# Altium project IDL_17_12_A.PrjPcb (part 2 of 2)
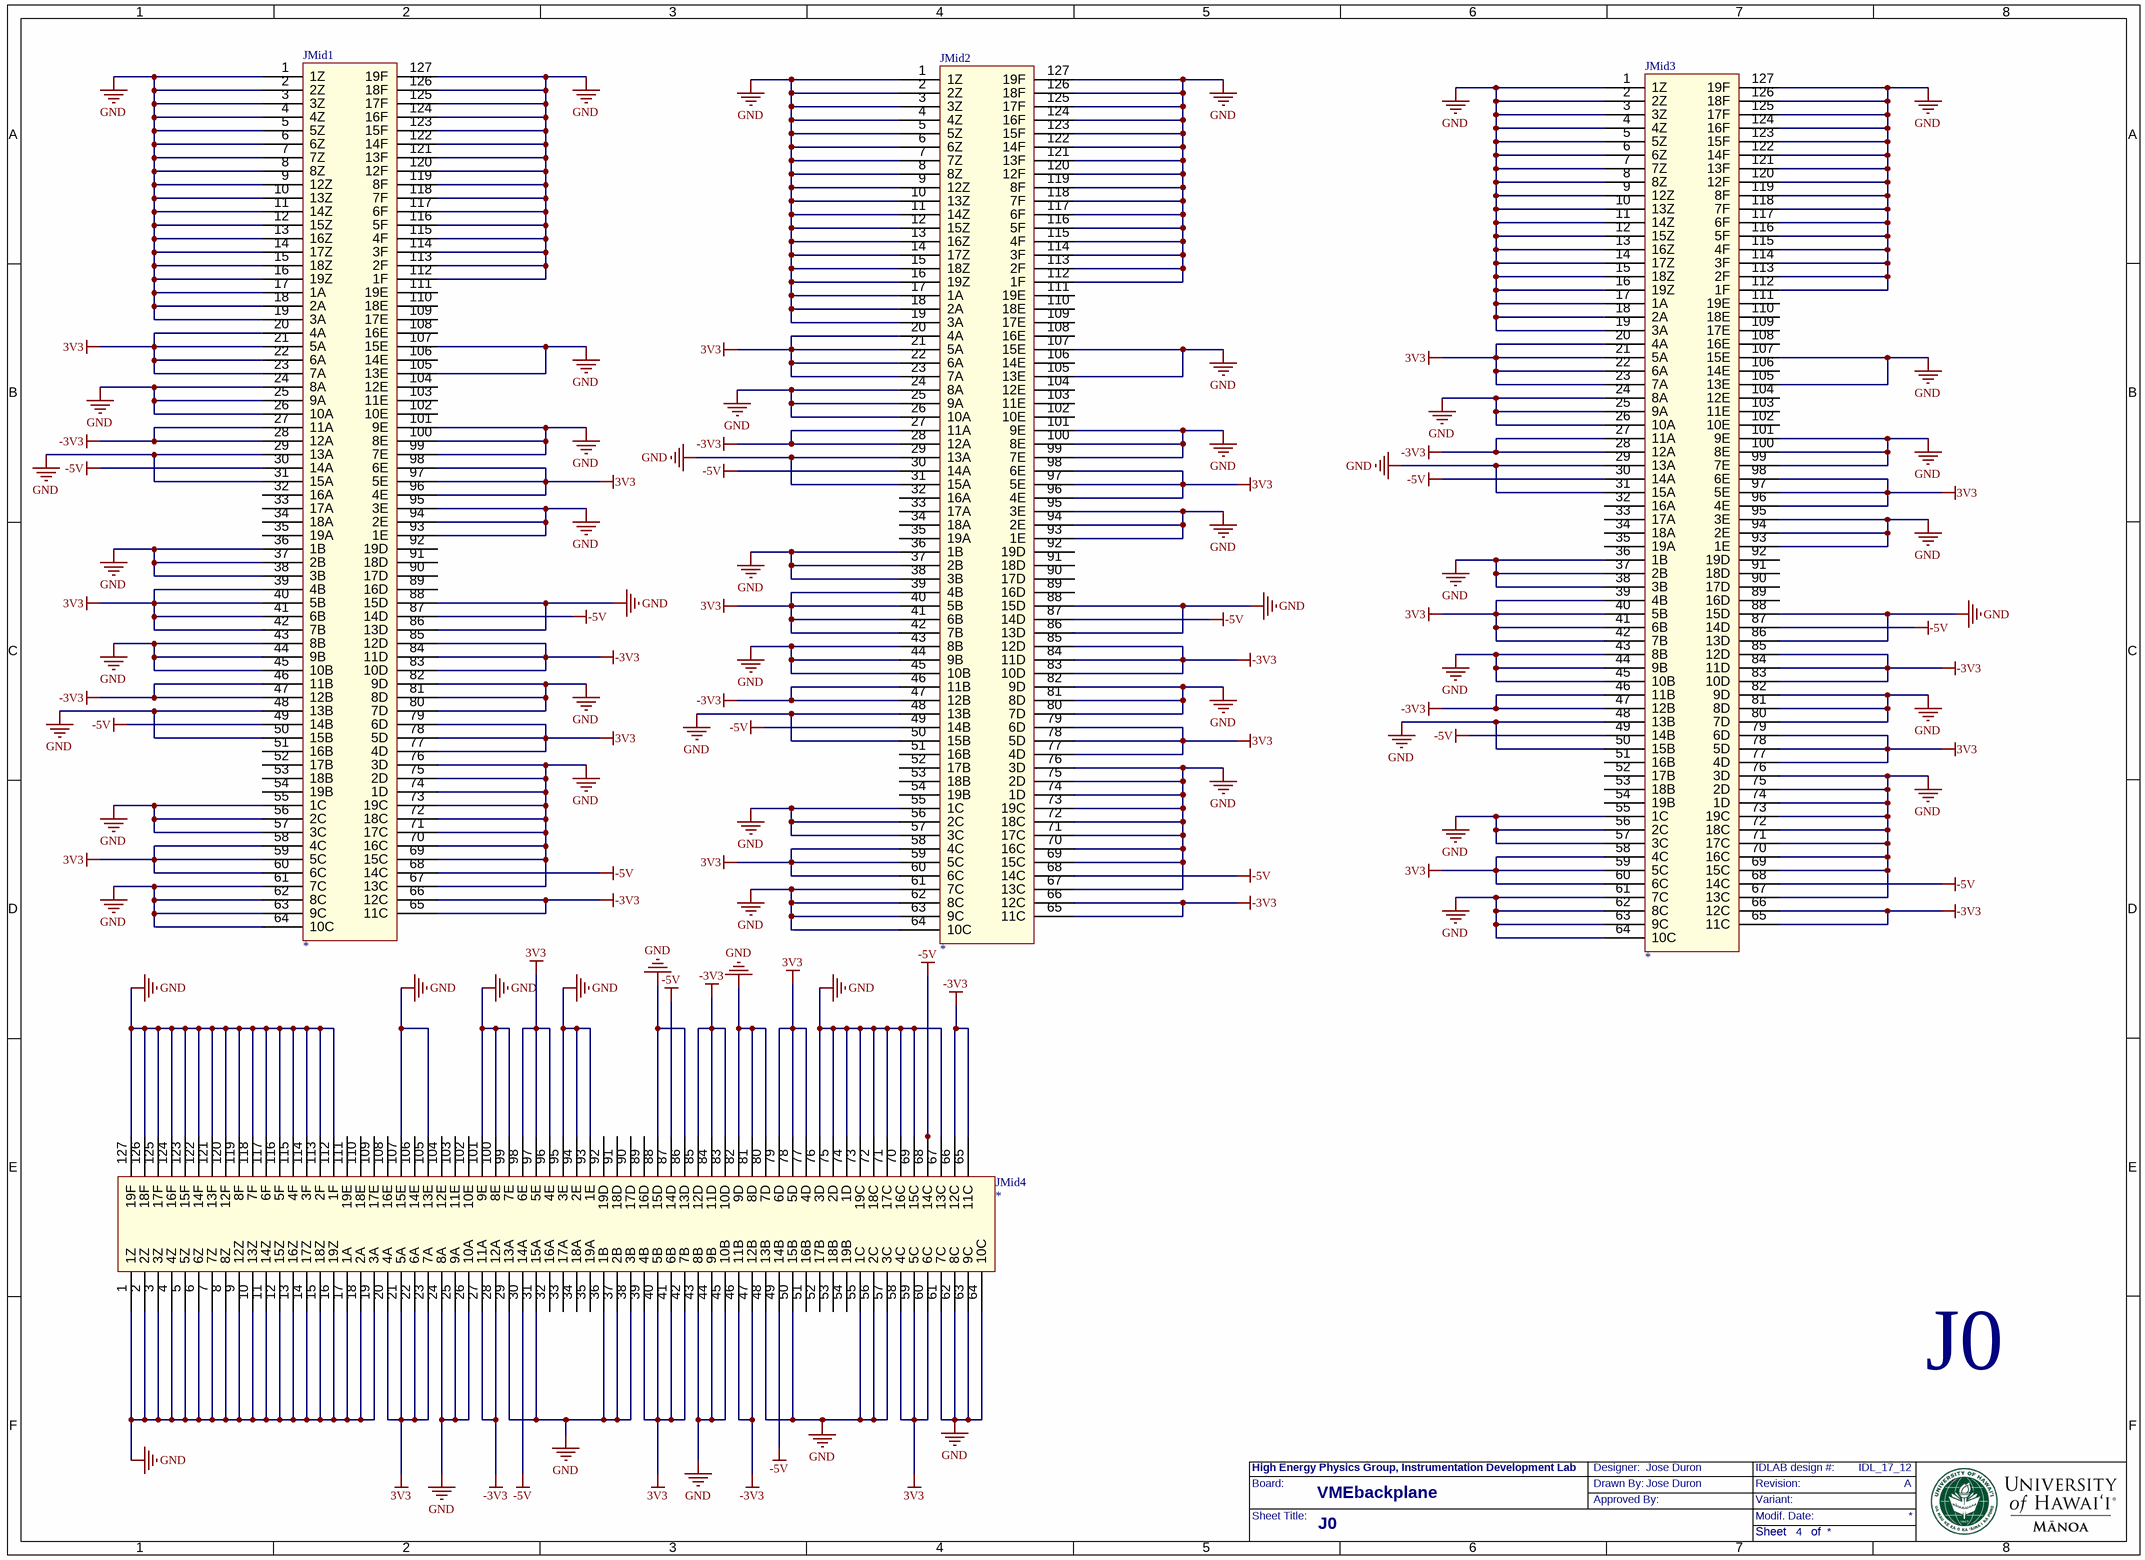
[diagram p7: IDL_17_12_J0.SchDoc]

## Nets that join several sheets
3V3: IDL_17_12_Top (5 pins), IDL_17_12_J0 (68 pins)
5V: IDL_17_12_Top (5 pins), IDL_17_12_J1 (16 pins), IDL_17_12_J2 (12 pins), IDL_IDL_17_12_VME/IDL_17_12_TerA1 (CR_IDL_17_12_TerA1.2 R1R_IDL_17_12_TerA1.2), IDL_IDL_17_12_VME/IDL_17_12_TerA2 (CR_IDL_17_12_TerA2.2 R1R_IDL_17_12_TerA2.2), IDL_IDL_17_12_VME/IDL_17_12_TerA3 (CR_IDL_17_12_TerA3.2 R1R_IDL_17_12_TerA3.2), IDL_IDL_17_12_VME/IDL_17_12_TerA4 (CR_IDL_17_12_TerA4.2 R1R_IDL_17_12_TerA4.2), IDL_IDL_17_12_VME/IDL_17_12_TerA5 (CR_IDL_17_12_TerA5.2 R1R_IDL_17_12_TerA5.2), IDL_IDL_17_12_VME/IDL_17_12_TerA6 (CR_IDL_17_12_TerA6.2 R1R_IDL_17_12_TerA6.2), IDL_IDL_17_12_VME/IDL_17_12_TerA7 (CR_IDL_17_12_TerA7.2 R1R_IDL_17_12_TerA7.2), IDL_IDL_17_12_VME/IDL_17_12_TerA8 (CR_IDL_17_12_TerA8.2 R1R_IDL_17_12_TerA8.2), IDL_IDL_17_12_VME/IDL_17_12_TerA9 (CR_IDL_17_12_TerA9.2 R1R_IDL_17_12_TerA9.2), IDL_IDL_17_12_VME/IDL_17_12_TerA10 (CR_IDL_17_12_TerA10.2 R1R_IDL_17_12_TerA10.2), IDL_IDL_17_12_VME/IDL_17_12_TerA11 (CR_IDL_17_12_TerA11.2 R1R_IDL_17_12_TerA11.2), IDL_IDL_17_12_VME/IDL_17_12_TerA12 (CR_IDL_17_12_TerA12.2 R1R_IDL_17_12_TerA12.2), IDL_IDL_17_12_VME/IDL_17_12_TerA13 (CR_IDL_17_12_TerA13.2 R1R_IDL_17_12_TerA13.2), IDL_IDL_17_12_VME/IDL_17_12_TerA14 (CR_IDL_17_12_TerA14.2 R1R_IDL_17_12_TerA14.2), IDL_IDL_17_12_VME/IDL_17_12_TerA15 (CR_IDL_17_12_TerA15.2 R1R_IDL_17_12_TerA15.2), IDL_IDL_17_12_VME/IDL_17_12_TerA16 (CR_IDL_17_12_TerA16.2 R1R_IDL_17_12_TerA16.2), IDL_IDL_17_12_VME/IDL_17_12_TerA17 (CR_IDL_17_12_TerA17.2 R1R_IDL_17_12_TerA17.2), IDL_IDL_17_12_VME/IDL_17_12_TerA18 (CR_IDL_17_12_TerA18.2 R1R_IDL_17_12_TerA18.2), IDL_IDL_17_12_VME/IDL_17_12_TerA19 (CR_IDL_17_12_TerA19.2 R1R_IDL_17_12_TerA19.2), IDL_IDL_17_12_VME/IDL_17_12_TerA20 (CR_IDL_17_12_TerA20.2 R1R_IDL_17_12_TerA20.2), IDL_IDL_17_12_VME/IDL_17_12_TerA21 (CR_IDL_17_12_TerA21.2 R1R_IDL_17_12_TerA21.2), IDL_IDL_17_12_VME/IDL_17_12_TerA22 (CR_IDL_17_12_TerA22.2 R1R_IDL_17_12_TerA22.2), IDL_IDL_17_12_VME/IDL_17_12_TerA23 (CR_IDL_17_12_TerA23.2 R1R_IDL_17_12_TerA23.2), IDL_IDL_17_12_VME/IDL_17_12_TerA24 (CR_IDL_17_12_TerA24.2 R1R_IDL_17_12_TerA24.2), IDL_IDL_17_12_VME/IDL_17_12_TerA25 (CR_IDL_17_12_TerA25.2 R1R_IDL_17_12_TerA25.2), IDL_IDL_17_12_VME/IDL_17_12_TerA26 (CR_IDL_17_12_TerA26.2 R1R_IDL_17_12_TerA26.2), IDL_IDL_17_12_VME/IDL_17_12_TerA27 (CR_IDL_17_12_TerA27.2 R1R_IDL_17_12_TerA27.2), IDL_IDL_17_12_VME/IDL_17_12_TerA28 (CR_IDL_17_12_TerA28.2 R1R_IDL_17_12_TerA28.2), IDL_IDL_17_12_VME/IDL_17_12_TerA29 (CR_IDL_17_12_TerA29.2 R1R_IDL_17_12_TerA29.2), IDL_IDL_17_12_VME/IDL_17_12_TerA30 (CR_IDL_17_12_TerA30.2 R1R_IDL_17_12_TerA30.2), IDL_IDL_17_12_VME/IDL_17_12_TerA31 (CR_IDL_17_12_TerA31.2 R1R_IDL_17_12_TerA31.2), IDL_IDL_17_12_VME/IDL_17_12_TerA32 (CR_IDL_17_12_TerA32.2 R1R_IDL_17_12_TerA32.2), IDL_IDL_17_12_VME/IDL_17_12_TerA33 (CR_IDL_17_12_TerA33.2 R1R_IDL_17_12_TerA33.2), IDL_IDL_17_12_VME/IDL_17_12_TerA34 (CR_IDL_17_12_TerA34.2 R1R_IDL_17_12_TerA34.2), IDL_IDL_17_12_VME/IDL_17_12_TerA35 (CR_IDL_17_12_TerA35.2 R1R_IDL_17_12_TerA35.2), IDL_IDL_17_12_VME/IDL_17_12_TerA36 (CR_IDL_17_12_TerA36.2 R1R_IDL_17_12_TerA36.2), IDL_IDL_17_12_VME/IDL_17_12_TerA37 (CR_IDL_17_12_TerA37.2 R1R_IDL_17_12_TerA37.2), IDL_IDL_17_12_VME/IDL_17_12_TerA38 (CR_IDL_17_12_TerA38.2 R1R_IDL_17_12_TerA38.2), IDL_IDL_17_12_VME/IDL_17_12_TerA39 (CR_IDL_17_12_TerA39.2 R1R_IDL_17_12_TerA39.2), IDL_IDL_17_12_VME/IDL_17_12_TerA40 (CR_IDL_17_12_TerA40.2 R1R_IDL_17_12_TerA40.2), IDL_IDL_17_12_VME/IDL_17_12_TerA41 (CR_IDL_17_12_TerA41.2 R1R_IDL_17_12_TerA41.2), IDL_IDL_17_12_VME/IDL_17_12_TerA42 (CR_IDL_17_12_TerA42.2 R1R_IDL_17_12_TerA42.2), IDL_IDL_17_12_VME/IDL_17_12_TerA43 (CR_IDL_17_12_TerA43.2 R1R_IDL_17_12_TerA43.2), IDL_IDL_17_12_VME/IDL_17_12_TerA44 (CR_IDL_17_12_TerA44.2 R1R_IDL_17_12_TerA44.2), IDL_IDL_17_12_VME/IDL_17_12_TerA45 (CR_IDL_17_12_TerA45.2 R1R_IDL_17_12_TerA45.2), IDL_IDL_17_12_VME/IDL_17_12_TerA46 (CR_IDL_17_12_TerA46.2 R1R_IDL_17_12_TerA46.2), IDL_IDL_17_12_VME/IDL_17_12_TerA47 (CR_IDL_17_12_TerA47.2 R1R_IDL_17_12_TerA47.2), IDL_IDL_17_12_VME/IDL_17_12_TerA48 (CR_IDL_17_12_TerA48.2 R1R_IDL_17_12_TerA48.2), IDL_IDL_17_12_VME/IDL_17_12_TerA49 (CR_IDL_17_12_TerA49.2 R1R_IDL_17_12_TerA49.2), IDL_IDL_17_12_VME/IDL_17_12_TerA50 (CR_IDL_17_12_TerA50.2 R1R_IDL_17_12_TerA50.2), IDL_IDL_17_12_VME/IDL_17_12_TerA51 (CR_IDL_17_12_TerA51.2 R1R_IDL_17_12_TerA51.2), IDL_IDL_17_12_VME/IDL_17_12_TerA52 (CR_IDL_17_12_TerA52.2 R1R_IDL_17_12_TerA52.2), IDL_IDL_17_12_VME/IDL_17_12_TerA53 (CR_IDL_17_12_TerA53.2 R1R_IDL_17_12_TerA53.2), IDL_IDL_17_12_VME/IDL_17_12_TerA54 (CR_IDL_17_12_TerA54.2 R1R_IDL_17_12_TerA54.2), IDL_IDL_17_12_VME/IDL_17_12_TerA55 (CR_IDL_17_12_TerA55.2 R1R_IDL_17_12_TerA55.2), IDL_IDL_17_12_VME/IDL_17_12_TerA56 (CR_IDL_17_12_TerA56.2 R1R_IDL_17_12_TerA56.2), IDL_IDL_17_12_VME/IDL_17_12_TerA57 (CR_IDL_17_12_TerA57.2 R1R_IDL_17_12_TerA57.2), IDL_IDL_17_12_VME/IDL_17_12_TerA58 (CR_IDL_17_12_TerA58.2 R1R_IDL_17_12_TerA58.2), IDL_IDL_17_12_VME/IDL_17_12_TerA59 (CR_IDL_17_12_TerA59.2 R1R_IDL_17_12_TerA59.2), IDL_IDL_17_12_VME/IDL_17_12_TerA60 (CR_IDL_17_12_TerA60.2 R1R_IDL_17_12_TerA60.2), IDL_IDL_17_12_VME/IDL_17_12_TerA61 (CR_IDL_17_12_TerA61.2 R1R_IDL_17_12_TerA61.2), IDL_IDL_17_12_VME/IDL_17_12_TerA62 (CR_IDL_17_12_TerA62.2 R1R_IDL_17_12_TerA62.2), IDL_IDL_17_12_VME/IDL_17_12_TerA63 (CR_IDL_17_12_TerA63.2 R1R_IDL_17_12_TerA63.2), IDL_IDL_17_12_VME/IDL_17_12_TerA64 (CR_IDL_17_12_TerA64.2 R1R_IDL_17_12_TerA64.2), IDL_IDL_17_12_VME/IDL_17_12_TerA65 (CR_IDL_17_12_TerA65.2 R1R_IDL_17_12_TerA65.2), IDL_IDL_17_12_VME/IDL_17_12_TerA66 (CR_IDL_17_12_TerA66.2 R1R_IDL_17_12_TerA66.2), IDL_IDL_17_12_VME/IDL_17_12_TerA67 (CR_IDL_17_12_TerA67.2 R1R_IDL_17_12_TerA67.2), IDL_IDL_17_12_VME/IDL_17_12_TerA68 (CR_IDL_17_12_TerA68.2 R1R_IDL_17_12_TerA68.2), IDL_IDL_17_12_VME/IDL_17_12_TerA69 (CR_IDL_17_12_TerA69.2 R1R_IDL_17_12_TerA69.2), IDL_IDL_17_12_VME/IDL_17_12_TerA70 (CR_IDL_17_12_TerA70.2 R1R_IDL_17_12_TerA70.2), IDL_IDL_17_12_VME/IDL_17_12_TerA71 (CR_IDL_17_12_TerA71.2 R1R_IDL_17_12_TerA71.2), IDL_IDL_17_12_VME/IDL_17_12_TerA72 (CR_IDL_17_12_TerA72.2 R1R_IDL_17_12_TerA72.2), IDL_IDL_17_12_VME/IDL_17_12_TerB1 (CRB_IDL_17_12_TerB1.2 R1RB_IDL_17_12_TerB1.2), IDL_IDL_17_12_VME/IDL_17_12_TerB2 (CRB_IDL_17_12_TerB2.2 R1RB_IDL_17_12_TerB2.2), IDL_IDL_17_12_VME/IDL_17_12_TerB3 (CRB_IDL_17_12_TerB3.2 R1RB_IDL_17_12_TerB3.2), IDL_IDL_17_12_VME/IDL_17_12_TerB4 (CRB_IDL_17_12_TerB4.2 R1RB_IDL_17_12_TerB4.2), IDL_IDL_17_12_VME/IDL_17_12_TerB5 (CRB_IDL_17_12_TerB5.2 R1RB_IDL_17_12_TerB5.2), IDL_IDL_17_12_VME/IDL_17_12_TerB6 (CRB_IDL_17_12_TerB6.2 R1RB_IDL_17_12_TerB6.2), IDL_IDL_17_12_VME/IDL_17_12_TerB7 (CRB_IDL_17_12_TerB7.2 R1RB_IDL_17_12_TerB7.2), IDL_IDL_17_12_VME/IDL_17_12_TerB8 (CRB_IDL_17_12_TerB8.2 R1RB_IDL_17_12_TerB8.2), IDL_IDL_17_12_VME/IDL_17_12_TerB9 (CRB_IDL_17_12_TerB9.2 R1RB_IDL_17_12_TerB9.2), IDL_IDL_17_12_VME/IDL_17_12_TerB10 (CRB_IDL_17_12_TerB10.2 R1RB_IDL_17_12_TerB10.2), IDL_IDL_17_12_VME/IDL_17_12_TerB11 (CRB_IDL_17_12_TerB11.2 R1RB_IDL_17_12_TerB11.2), IDL_IDL_17_12_VME/IDL_17_12_TerB12 (CRB_IDL_17_12_TerB12.2 R1RB_IDL_17_12_TerB12.2), IDL_IDL_17_12_VME/IDL_17_12_TerB13 (CRB_IDL_17_12_TerB13.2 R1RB_IDL_17_12_TerB13.2), IDL_IDL_17_12_VME/IDL_17_12_TerB14 (CRB_IDL_17_12_TerB14.2 R1RB_IDL_17_12_TerB14.2), IDL_IDL_17_12_VME/IDL_17_12_TerB15 (CRB_IDL_17_12_TerB15.2 R1RB_IDL_17_12_TerB15.2), IDL_IDL_17_12_VME/IDL_17_12_TerB16 (CRB_IDL_17_12_TerB16.2 R1RB_IDL_17_12_TerB16.2), IDL_IDL_17_12_VME/IDL_17_12_TerB17 (CRB_IDL_17_12_TerB17.2 R1RB_IDL_17_12_TerB17.2), IDL_IDL_17_12_VME/IDL_17_12_TerB18 (CRB_IDL_17_12_TerB18.2 R1RB_IDL_17_12_TerB18.2), IDL_IDL_17_12_VME/IDL_17_12_TerB19 (CRB_IDL_17_12_TerB19.2 R1RB_IDL_17_12_TerB19.2), IDL_IDL_17_12_VME/IDL_17_12_TerB20 (CRB_IDL_17_12_TerB20.2 R1RB_IDL_17_12_TerB20.2), IDL_IDL_17_12_VME/IDL_17_12_TerB21 (CRB_IDL_17_12_TerB21.2 R1RB_IDL_17_12_TerB21.2), IDL_IDL_17_12_VME/IDL_17_12_TerB22 (CRB_IDL_17_12_TerB22.2 R1RB_IDL_17_12_TerB22.2), IDL_IDL_17_12_VME/IDL_17_12_TerB23 (CRB_IDL_17_12_TerB23.2 R1RB_IDL_17_12_TerB23.2), IDL_IDL_17_12_VME/IDL_17_12_TerB24 (CRB_IDL_17_12_TerB24.2 R1RB_IDL_17_12_TerB24.2), IDL_IDL_17_12_VME/IDL_17_12_TerB25 (CRB_IDL_17_12_TerB25.2 R1RB_IDL_17_12_TerB25.2)
12V: IDL_17_12_Top (5 pins), IDL_17_12_J1 (Jtop1.c31 Jtop2.c31 Jtop3.c31 Jtop4.c31)
-3V3: IDL_17_12_Top (5 pins), IDL_17_12_J0 (36 pins)
-5V: IDL_17_12_Top (5 pins), IDL_17_12_J0 (16 pins)
-12V: IDL_17_12_Top (5 pins), IDL_17_12_J1 (Jtop1.a31 Jtop2.a31 Jtop3.a31 Jtop4.a31)
GND: IDL_17_12_Top (GND.1 GND.2 GND.3 GND.4), IDL_17_12_J1 (32 pins), IDL_17_12_J2 (16 pins), IDL_IDL_17_12_VME/IDL_17_12_TerA1 (CR_IDL_17_12_TerA1.1 R2R_IDL_17_12_TerA1.1), IDL_IDL_17_12_VME/IDL_17_12_TerA2 (CR_IDL_17_12_TerA2.1 R2R_IDL_17_12_TerA2.1), IDL_IDL_17_12_VME/IDL_17_12_TerA3 (CR_IDL_17_12_TerA3.1 R2R_IDL_17_12_TerA3.1), IDL_IDL_17_12_VME/IDL_17_12_TerA4 (CR_IDL_17_12_TerA4.1 R2R_IDL_17_12_TerA4.1), IDL_IDL_17_12_VME/IDL_17_12_TerA5 (CR_IDL_17_12_TerA5.1 R2R_IDL_17_12_TerA5.1), IDL_IDL_17_12_VME/IDL_17_12_TerA6 (CR_IDL_17_12_TerA6.1 R2R_IDL_17_12_TerA6.1), IDL_IDL_17_12_VME/IDL_17_12_TerA7 (CR_IDL_17_12_TerA7.1 R2R_IDL_17_12_TerA7.1), IDL_IDL_17_12_VME/IDL_17_12_TerA8 (CR_IDL_17_12_TerA8.1 R2R_IDL_17_12_TerA8.1), IDL_IDL_17_12_VME/IDL_17_12_TerA9 (CR_IDL_17_12_TerA9.1 R2R_IDL_17_12_TerA9.1), IDL_IDL_17_12_VME/IDL_17_12_TerA10 (CR_IDL_17_12_TerA10.1 R2R_IDL_17_12_TerA10.1), IDL_IDL_17_12_VME/IDL_17_12_TerA11 (CR_IDL_17_12_TerA11.1 R2R_IDL_17_12_TerA11.1), IDL_IDL_17_12_VME/IDL_17_12_TerA12 (CR_IDL_17_12_TerA12.1 R2R_IDL_17_12_TerA12.1), IDL_IDL_17_12_VME/IDL_17_12_TerA13 (CR_IDL_17_12_TerA13.1 R2R_IDL_17_12_TerA13.1), IDL_IDL_17_12_VME/IDL_17_12_TerA14 (CR_IDL_17_12_TerA14.1 R2R_IDL_17_12_TerA14.1), IDL_IDL_17_12_VME/IDL_17_12_TerA15 (CR_IDL_17_12_TerA15.1 R2R_IDL_17_12_TerA15.1), IDL_IDL_17_12_VME/IDL_17_12_TerA16 (CR_IDL_17_12_TerA16.1 R2R_IDL_17_12_TerA16.1), IDL_IDL_17_12_VME/IDL_17_12_TerA17 (CR_IDL_17_12_TerA17.1 R2R_IDL_17_12_TerA17.1), IDL_IDL_17_12_VME/IDL_17_12_TerA18 (CR_IDL_17_12_TerA18.1 R2R_IDL_17_12_TerA18.1), IDL_IDL_17_12_VME/IDL_17_12_TerA19 (CR_IDL_17_12_TerA19.1 R2R_IDL_17_12_TerA19.1), IDL_IDL_17_12_VME/IDL_17_12_TerA20 (CR_IDL_17_12_TerA20.1 R2R_IDL_17_12_TerA20.1), IDL_IDL_17_12_VME/IDL_17_12_TerA21 (CR_IDL_17_12_TerA21.1 R2R_IDL_17_12_TerA21.1), IDL_IDL_17_12_VME/IDL_17_12_TerA22 (CR_IDL_17_12_TerA22.1 R2R_IDL_17_12_TerA22.1), IDL_IDL_17_12_VME/IDL_17_12_TerA23 (CR_IDL_17_12_TerA23.1 R2R_IDL_17_12_TerA23.1), IDL_IDL_17_12_VME/IDL_17_12_TerA24 (CR_IDL_17_12_TerA24.1 R2R_IDL_17_12_TerA24.1), IDL_IDL_17_12_VME/IDL_17_12_TerA25 (CR_IDL_17_12_TerA25.1 R2R_IDL_17_12_TerA25.1), IDL_IDL_17_12_VME/IDL_17_12_TerA26 (CR_IDL_17_12_TerA26.1 R2R_IDL_17_12_TerA26.1), IDL_IDL_17_12_VME/IDL_17_12_TerA27 (CR_IDL_17_12_TerA27.1 R2R_IDL_17_12_TerA27.1), IDL_IDL_17_12_VME/IDL_17_12_TerA28 (CR_IDL_17_12_TerA28.1 R2R_IDL_17_12_TerA28.1), IDL_IDL_17_12_VME/IDL_17_12_TerA29 (CR_IDL_17_12_TerA29.1 R2R_IDL_17_12_TerA29.1), IDL_IDL_17_12_VME/IDL_17_12_TerA30 (CR_IDL_17_12_TerA30.1 R2R_IDL_17_12_TerA30.1), IDL_IDL_17_12_VME/IDL_17_12_TerA31 (CR_IDL_17_12_TerA31.1 R2R_IDL_17_12_TerA31.1), IDL_IDL_17_12_VME/IDL_17_12_TerA32 (CR_IDL_17_12_TerA32.1 R2R_IDL_17_12_TerA32.1), IDL_IDL_17_12_VME/IDL_17_12_TerA33 (CR_IDL_17_12_TerA33.1 R2R_IDL_17_12_TerA33.1), IDL_IDL_17_12_VME/IDL_17_12_TerA34 (CR_IDL_17_12_TerA34.1 R2R_IDL_17_12_TerA34.1), IDL_IDL_17_12_VME/IDL_17_12_TerA35 (CR_IDL_17_12_TerA35.1 R2R_IDL_17_12_TerA35.1), IDL_IDL_17_12_VME/IDL_17_12_TerA36 (CR_IDL_17_12_TerA36.1 R2R_IDL_17_12_TerA36.1), IDL_IDL_17_12_VME/IDL_17_12_TerA37 (CR_IDL_17_12_TerA37.1 R2R_IDL_17_12_TerA37.1), IDL_IDL_17_12_VME/IDL_17_12_TerA38 (CR_IDL_17_12_TerA38.1 R2R_IDL_17_12_TerA38.1), IDL_IDL_17_12_VME/IDL_17_12_TerA39 (CR_IDL_17_12_TerA39.1 R2R_IDL_17_12_TerA39.1), IDL_IDL_17_12_VME/IDL_17_12_TerA40 (CR_IDL_17_12_TerA40.1 R2R_IDL_17_12_TerA40.1), IDL_IDL_17_12_VME/IDL_17_12_TerA41 (CR_IDL_17_12_TerA41.1 R2R_IDL_17_12_TerA41.1), IDL_IDL_17_12_VME/IDL_17_12_TerA42 (CR_IDL_17_12_TerA42.1 R2R_IDL_17_12_TerA42.1), IDL_IDL_17_12_VME/IDL_17_12_TerA43 (CR_IDL_17_12_TerA43.1 R2R_IDL_17_12_TerA43.1), IDL_IDL_17_12_VME/IDL_17_12_TerA44 (CR_IDL_17_12_TerA44.1 R2R_IDL_17_12_TerA44.1), IDL_IDL_17_12_VME/IDL_17_12_TerA45 (CR_IDL_17_12_TerA45.1 R2R_IDL_17_12_TerA45.1), IDL_IDL_17_12_VME/IDL_17_12_TerA46 (CR_IDL_17_12_TerA46.1 R2R_IDL_17_12_TerA46.1), IDL_IDL_17_12_VME/IDL_17_12_TerA47 (CR_IDL_17_12_TerA47.1 R2R_IDL_17_12_TerA47.1), IDL_IDL_17_12_VME/IDL_17_12_TerA48 (CR_IDL_17_12_TerA48.1 R2R_IDL_17_12_TerA48.1), IDL_IDL_17_12_VME/IDL_17_12_TerA49 (CR_IDL_17_12_TerA49.1 R2R_IDL_17_12_TerA49.1), IDL_IDL_17_12_VME/IDL_17_12_TerA50 (CR_IDL_17_12_TerA50.1 R2R_IDL_17_12_TerA50.1), IDL_IDL_17_12_VME/IDL_17_12_TerA51 (CR_IDL_17_12_TerA51.1 R2R_IDL_17_12_TerA51.1), IDL_IDL_17_12_VME/IDL_17_12_TerA52 (CR_IDL_17_12_TerA52.1 R2R_IDL_17_12_TerA52.1), IDL_IDL_17_12_VME/IDL_17_12_TerA53 (CR_IDL_17_12_TerA53.1 R2R_IDL_17_12_TerA53.1), IDL_IDL_17_12_VME/IDL_17_12_TerA54 (CR_IDL_17_12_TerA54.1 R2R_IDL_17_12_TerA54.1), IDL_IDL_17_12_VME/IDL_17_12_TerA55 (CR_IDL_17_12_TerA55.1 R2R_IDL_17_12_TerA55.1), IDL_IDL_17_12_VME/IDL_17_12_TerA56 (CR_IDL_17_12_TerA56.1 R2R_IDL_17_12_TerA56.1), IDL_IDL_17_12_VME/IDL_17_12_TerA57 (CR_IDL_17_12_TerA57.1 R2R_IDL_17_12_TerA57.1), IDL_IDL_17_12_VME/IDL_17_12_TerA58 (CR_IDL_17_12_TerA58.1 R2R_IDL_17_12_TerA58.1), IDL_IDL_17_12_VME/IDL_17_12_TerA59 (CR_IDL_17_12_TerA59.1 R2R_IDL_17_12_TerA59.1), IDL_IDL_17_12_VME/IDL_17_12_TerA60 (CR_IDL_17_12_TerA60.1 R2R_IDL_17_12_TerA60.1), IDL_IDL_17_12_VME/IDL_17_12_TerA61 (CR_IDL_17_12_TerA61.1 R2R_IDL_17_12_TerA61.1), IDL_IDL_17_12_VME/IDL_17_12_TerA62 (CR_IDL_17_12_TerA62.1 R2R_IDL_17_12_TerA62.1), IDL_IDL_17_12_VME/IDL_17_12_TerA63 (CR_IDL_17_12_TerA63.1 R2R_IDL_17_12_TerA63.1), IDL_IDL_17_12_VME/IDL_17_12_TerA64 (CR_IDL_17_12_TerA64.1 R2R_IDL_17_12_TerA64.1), IDL_IDL_17_12_VME/IDL_17_12_TerA65 (CR_IDL_17_12_TerA65.1 R2R_IDL_17_12_TerA65.1), IDL_IDL_17_12_VME/IDL_17_12_TerA66 (CR_IDL_17_12_TerA66.1 R2R_IDL_17_12_TerA66.1), IDL_IDL_17_12_VME/IDL_17_12_TerA67 (CR_IDL_17_12_TerA67.1 R2R_IDL_17_12_TerA67.1), IDL_IDL_17_12_VME/IDL_17_12_TerA68 (CR_IDL_17_12_TerA68.1 R2R_IDL_17_12_TerA68.1), IDL_IDL_17_12_VME/IDL_17_12_TerA69 (CR_IDL_17_12_TerA69.1 R2R_IDL_17_12_TerA69.1), IDL_IDL_17_12_VME/IDL_17_12_TerA70 (CR_IDL_17_12_TerA70.1 R2R_IDL_17_12_TerA70.1), IDL_IDL_17_12_VME/IDL_17_12_TerA71 (CR_IDL_17_12_TerA71.1 R2R_IDL_17_12_TerA71.1), IDL_IDL_17_12_VME/IDL_17_12_TerA72 (CR_IDL_17_12_TerA72.1 R2R_IDL_17_12_TerA72.1), IDL_IDL_17_12_VME/IDL_17_12_TerB1 (CRB_IDL_17_12_TerB1.1 R2RB_IDL_17_12_TerB1.1), IDL_IDL_17_12_VME/IDL_17_12_TerB2 (CRB_IDL_17_12_TerB2.1 R2RB_IDL_17_12_TerB2.1), IDL_IDL_17_12_VME/IDL_17_12_TerB3 (CRB_IDL_17_12_TerB3.1 R2RB_IDL_17_12_TerB3.1), IDL_IDL_17_12_VME/IDL_17_12_TerB4 (CRB_IDL_17_12_TerB4.1 R2RB_IDL_17_12_TerB4.1), IDL_IDL_17_12_VME/IDL_17_12_TerB5 (CRB_IDL_17_12_TerB5.1 R2RB_IDL_17_12_TerB5.1), IDL_IDL_17_12_VME/IDL_17_12_TerB6 (CRB_IDL_17_12_TerB6.1 R2RB_IDL_17_12_TerB6.1), IDL_IDL_17_12_VME/IDL_17_12_TerB7 (CRB_IDL_17_12_TerB7.1 R2RB_IDL_17_12_TerB7.1), IDL_IDL_17_12_VME/IDL_17_12_TerB8 (CRB_IDL_17_12_TerB8.1 R2RB_IDL_17_12_TerB8.1), IDL_IDL_17_12_VME/IDL_17_12_TerB9 (CRB_IDL_17_12_TerB9.1 R2RB_IDL_17_12_TerB9.1), IDL_IDL_17_12_VME/IDL_17_12_TerB10 (CRB_IDL_17_12_TerB10.1 R2RB_IDL_17_12_TerB10.1), IDL_IDL_17_12_VME/IDL_17_12_TerB11 (CRB_IDL_17_12_TerB11.1 R2RB_IDL_17_12_TerB11.1), IDL_IDL_17_12_VME/IDL_17_12_TerB12 (CRB_IDL_17_12_TerB12.1 R2RB_IDL_17_12_TerB12.1), IDL_IDL_17_12_VME/IDL_17_12_TerB13 (CRB_IDL_17_12_TerB13.1 R2RB_IDL_17_12_TerB13.1), IDL_IDL_17_12_VME/IDL_17_12_TerB14 (CRB_IDL_17_12_TerB14.1 R2RB_IDL_17_12_TerB14.1), IDL_IDL_17_12_VME/IDL_17_12_TerB15 (CRB_IDL_17_12_TerB15.1 R2RB_IDL_17_12_TerB15.1), IDL_IDL_17_12_VME/IDL_17_12_TerB16 (CRB_IDL_17_12_TerB16.1 R2RB_IDL_17_12_TerB16.1), IDL_IDL_17_12_VME/IDL_17_12_TerB17 (CRB_IDL_17_12_TerB17.1 R2RB_IDL_17_12_TerB17.1), IDL_IDL_17_12_VME/IDL_17_12_TerB18 (CRB_IDL_17_12_TerB18.1 R2RB_IDL_17_12_TerB18.1), IDL_IDL_17_12_VME/IDL_17_12_TerB19 (CRB_IDL_17_12_TerB19.1 R2RB_IDL_17_12_TerB19.1), IDL_IDL_17_12_VME/IDL_17_12_TerB20 (CRB_IDL_17_12_TerB20.1 R2RB_IDL_17_12_TerB20.1), IDL_IDL_17_12_VME/IDL_17_12_TerB21 (CRB_IDL_17_12_TerB21.1 R2RB_IDL_17_12_TerB21.1), IDL_IDL_17_12_VME/IDL_17_12_TerB22 (CRB_IDL_17_12_TerB22.1 R2RB_IDL_17_12_TerB22.1), IDL_IDL_17_12_VME/IDL_17_12_TerB23 (CRB_IDL_17_12_TerB23.1 R2RB_IDL_17_12_TerB23.1), IDL_IDL_17_12_VME/IDL_17_12_TerB24 (CRB_IDL_17_12_TerB24.1 R2RB_IDL_17_12_TerB24.1), IDL_IDL_17_12_VME/IDL_17_12_TerB25 (CRB_IDL_17_12_TerB25.1 R2RB_IDL_17_12_TerB25.1), IDL_17_12_J0 (308 pins)
A: IDL_IDL_17_12_VME/IDL_17_12_TerA1 (R1R_IDL_17_12_TerA1.1 R2R_IDL_17_12_TerA1.2), IDL_IDL_17_12_VME/IDL_17_12_TerA2 (R1R_IDL_17_12_TerA2.1 R2R_IDL_17_12_TerA2.2), IDL_IDL_17_12_VME/IDL_17_12_TerA3 (R1R_IDL_17_12_TerA3.1 R2R_IDL_17_12_TerA3.2), IDL_IDL_17_12_VME/IDL_17_12_TerA4 (R1R_IDL_17_12_TerA4.1 R2R_IDL_17_12_TerA4.2), IDL_IDL_17_12_VME/IDL_17_12_TerA5 (R1R_IDL_17_12_TerA5.1 R2R_IDL_17_12_TerA5.2), IDL_IDL_17_12_VME/IDL_17_12_TerA6 (R1R_IDL_17_12_TerA6.1 R2R_IDL_17_12_TerA6.2), IDL_IDL_17_12_VME/IDL_17_12_TerA7 (R1R_IDL_17_12_TerA7.1 R2R_IDL_17_12_TerA7.2), IDL_IDL_17_12_VME/IDL_17_12_TerA8 (R1R_IDL_17_12_TerA8.1 R2R_IDL_17_12_TerA8.2), IDL_IDL_17_12_VME/IDL_17_12_TerA9 (R1R_IDL_17_12_TerA9.1 R2R_IDL_17_12_TerA9.2), IDL_IDL_17_12_VME/IDL_17_12_TerA10 (R1R_IDL_17_12_TerA10.1 R2R_IDL_17_12_TerA10.2), IDL_IDL_17_12_VME/IDL_17_12_TerA11 (R1R_IDL_17_12_TerA11.1 R2R_IDL_17_12_TerA11.2), IDL_IDL_17_12_VME/IDL_17_12_TerA12 (R1R_IDL_17_12_TerA12.1 R2R_IDL_17_12_TerA12.2), IDL_IDL_17_12_VME/IDL_17_12_TerA13 (R1R_IDL_17_12_TerA13.1 R2R_IDL_17_12_TerA13.2), IDL_IDL_17_12_VME/IDL_17_12_TerA14 (R1R_IDL_17_12_TerA14.1 R2R_IDL_17_12_TerA14.2), IDL_IDL_17_12_VME/IDL_17_12_TerA15 (R1R_IDL_17_12_TerA15.1 R2R_IDL_17_12_TerA15.2), IDL_IDL_17_12_VME/IDL_17_12_TerA16 (R1R_IDL_17_12_TerA16.1 R2R_IDL_17_12_TerA16.2), IDL_IDL_17_12_VME/IDL_17_12_TerA17 (R1R_IDL_17_12_TerA17.1 R2R_IDL_17_12_TerA17.2), IDL_IDL_17_12_VME/IDL_17_12_TerA18 (R1R_IDL_17_12_TerA18.1 R2R_IDL_17_12_TerA18.2), IDL_IDL_17_12_VME/IDL_17_12_TerA19 (R1R_IDL_17_12_TerA19.1 R2R_IDL_17_12_TerA19.2), IDL_IDL_17_12_VME/IDL_17_12_TerA20 (R1R_IDL_17_12_TerA20.1 R2R_IDL_17_12_TerA20.2), IDL_IDL_17_12_VME/IDL_17_12_TerA21 (R1R_IDL_17_12_TerA21.1 R2R_IDL_17_12_TerA21.2), IDL_IDL_17_12_VME/IDL_17_12_TerA22 (R1R_IDL_17_12_TerA22.1 R2R_IDL_17_12_TerA22.2), IDL_IDL_17_12_VME/IDL_17_12_TerA23 (R1R_IDL_17_12_TerA23.1 R2R_IDL_17_12_TerA23.2), IDL_IDL_17_12_VME/IDL_17_12_TerA24 (R1R_IDL_17_12_TerA24.1 R2R_IDL_17_12_TerA24.2), IDL_IDL_17_12_VME/IDL_17_12_TerA25 (R1R_IDL_17_12_TerA25.1 R2R_IDL_17_12_TerA25.2), IDL_IDL_17_12_VME/IDL_17_12_TerA26 (R1R_IDL_17_12_TerA26.1 R2R_IDL_17_12_TerA26.2), IDL_IDL_17_12_VME/IDL_17_12_TerA27 (R1R_IDL_17_12_TerA27.1 R2R_IDL_17_12_TerA27.2), IDL_IDL_17_12_VME/IDL_17_12_TerA28 (R1R_IDL_17_12_TerA28.1 R2R_IDL_17_12_TerA28.2), IDL_IDL_17_12_VME/IDL_17_12_TerA29 (R1R_IDL_17_12_TerA29.1 R2R_IDL_17_12_TerA29.2), IDL_IDL_17_12_VME/IDL_17_12_TerA30 (R1R_IDL_17_12_TerA30.1 R2R_IDL_17_12_TerA30.2), IDL_IDL_17_12_VME/IDL_17_12_TerA31 (R1R_IDL_17_12_TerA31.1 R2R_IDL_17_12_TerA31.2), IDL_IDL_17_12_VME/IDL_17_12_TerA32 (R1R_IDL_17_12_TerA32.1 R2R_IDL_17_12_TerA32.2), IDL_IDL_17_12_VME/IDL_17_12_TerA33 (R1R_IDL_17_12_TerA33.1 R2R_IDL_17_12_TerA33.2), IDL_IDL_17_12_VME/IDL_17_12_TerA34 (R1R_IDL_17_12_TerA34.1 R2R_IDL_17_12_TerA34.2), IDL_IDL_17_12_VME/IDL_17_12_TerA35 (R1R_IDL_17_12_TerA35.1 R2R_IDL_17_12_TerA35.2), IDL_IDL_17_12_VME/IDL_17_12_TerA36 (R1R_IDL_17_12_TerA36.1 R2R_IDL_17_12_TerA36.2), IDL_IDL_17_12_VME/IDL_17_12_TerA37 (R1R_IDL_17_12_TerA37.1 R2R_IDL_17_12_TerA37.2), IDL_IDL_17_12_VME/IDL_17_12_TerA38 (R1R_IDL_17_12_TerA38.1 R2R_IDL_17_12_TerA38.2), IDL_IDL_17_12_VME/IDL_17_12_TerA39 (R1R_IDL_17_12_TerA39.1 R2R_IDL_17_12_TerA39.2), IDL_IDL_17_12_VME/IDL_17_12_TerA40 (R1R_IDL_17_12_TerA40.1 R2R_IDL_17_12_TerA40.2), IDL_IDL_17_12_VME/IDL_17_12_TerA41 (R1R_IDL_17_12_TerA41.1 R2R_IDL_17_12_TerA41.2), IDL_IDL_17_12_VME/IDL_17_12_TerA42 (R1R_IDL_17_12_TerA42.1 R2R_IDL_17_12_TerA42.2), IDL_IDL_17_12_VME/IDL_17_12_TerA43 (R1R_IDL_17_12_TerA43.1 R2R_IDL_17_12_TerA43.2), IDL_IDL_17_12_VME/IDL_17_12_TerA44 (R1R_IDL_17_12_TerA44.1 R2R_IDL_17_12_TerA44.2), IDL_IDL_17_12_VME/IDL_17_12_TerA45 (R1R_IDL_17_12_TerA45.1 R2R_IDL_17_12_TerA45.2), IDL_IDL_17_12_VME/IDL_17_12_TerA46 (R1R_IDL_17_12_TerA46.1 R2R_IDL_17_12_TerA46.2), IDL_IDL_17_12_VME/IDL_17_12_TerA47 (R1R_IDL_17_12_TerA47.1 R2R_IDL_17_12_TerA47.2), IDL_IDL_17_12_VME/IDL_17_12_TerA48 (R1R_IDL_17_12_TerA48.1 R2R_IDL_17_12_TerA48.2), IDL_IDL_17_12_VME/IDL_17_12_TerA49 (R1R_IDL_17_12_TerA49.1 R2R_IDL_17_12_TerA49.2), IDL_IDL_17_12_VME/IDL_17_12_TerA50 (R1R_IDL_17_12_TerA50.1 R2R_IDL_17_12_TerA50.2), IDL_IDL_17_12_VME/IDL_17_12_TerA51 (R1R_IDL_17_12_TerA51.1 R2R_IDL_17_12_TerA51.2), IDL_IDL_17_12_VME/IDL_17_12_TerA52 (R1R_IDL_17_12_TerA52.1 R2R_IDL_17_12_TerA52.2), IDL_IDL_17_12_VME/IDL_17_12_TerA53 (R1R_IDL_17_12_TerA53.1 R2R_IDL_17_12_TerA53.2), IDL_IDL_17_12_VME/IDL_17_12_TerA54 (R1R_IDL_17_12_TerA54.1 R2R_IDL_17_12_TerA54.2), IDL_IDL_17_12_VME/IDL_17_12_TerA55 (R1R_IDL_17_12_TerA55.1 R2R_IDL_17_12_TerA55.2), IDL_IDL_17_12_VME/IDL_17_12_TerA56 (R1R_IDL_17_12_TerA56.1 R2R_IDL_17_12_TerA56.2), IDL_IDL_17_12_VME/IDL_17_12_TerA57 (R1R_IDL_17_12_TerA57.1 R2R_IDL_17_12_TerA57.2), IDL_IDL_17_12_VME/IDL_17_12_TerA58 (R1R_IDL_17_12_TerA58.1 R2R_IDL_17_12_TerA58.2), IDL_IDL_17_12_VME/IDL_17_12_TerA59 (R1R_IDL_17_12_TerA59.1 R2R_IDL_17_12_TerA59.2), IDL_IDL_17_12_VME/IDL_17_12_TerA60 (R1R_IDL_17_12_TerA60.1 R2R_IDL_17_12_TerA60.2), IDL_IDL_17_12_VME/IDL_17_12_TerA61 (R1R_IDL_17_12_TerA61.1 R2R_IDL_17_12_TerA61.2), IDL_IDL_17_12_VME/IDL_17_12_TerA62 (R1R_IDL_17_12_TerA62.1 R2R_IDL_17_12_TerA62.2), IDL_IDL_17_12_VME/IDL_17_12_TerA63 (R1R_IDL_17_12_TerA63.1 R2R_IDL_17_12_TerA63.2), IDL_IDL_17_12_VME/IDL_17_12_TerA64 (R1R_IDL_17_12_TerA64.1 R2R_IDL_17_12_TerA64.2), IDL_IDL_17_12_VME/IDL_17_12_TerA65 (R1R_IDL_17_12_TerA65.1 R2R_IDL_17_12_TerA65.2), IDL_IDL_17_12_VME/IDL_17_12_TerA66 (R1R_IDL_17_12_TerA66.1 R2R_IDL_17_12_TerA66.2), IDL_IDL_17_12_VME/IDL_17_12_TerA67 (R1R_IDL_17_12_TerA67.1 R2R_IDL_17_12_TerA67.2), IDL_IDL_17_12_VME/IDL_17_12_TerA68 (R1R_IDL_17_12_TerA68.1 R2R_IDL_17_12_TerA68.2), IDL_IDL_17_12_VME/IDL_17_12_TerA69 (R1R_IDL_17_12_TerA69.1 R2R_IDL_17_12_TerA69.2), IDL_IDL_17_12_VME/IDL_17_12_TerA70 (R1R_IDL_17_12_TerA70.1 R2R_IDL_17_12_TerA70.2), IDL_IDL_17_12_VME/IDL_17_12_TerA71 (R1R_IDL_17_12_TerA71.1 R2R_IDL_17_12_TerA71.2), IDL_IDL_17_12_VME/IDL_17_12_TerA72 (R1R_IDL_17_12_TerA72.1 R2R_IDL_17_12_TerA72.2)
B: IDL_IDL_17_12_VME/IDL_17_12_TerB1 (R1RB_IDL_17_12_TerB1.1 R2RB_IDL_17_12_TerB1.2), IDL_IDL_17_12_VME/IDL_17_12_TerB2 (R1RB_IDL_17_12_TerB2.1 R2RB_IDL_17_12_TerB2.2), IDL_IDL_17_12_VME/IDL_17_12_TerB3 (R1RB_IDL_17_12_TerB3.1 R2RB_IDL_17_12_TerB3.2), IDL_IDL_17_12_VME/IDL_17_12_TerB4 (R1RB_IDL_17_12_TerB4.1 R2RB_IDL_17_12_TerB4.2), IDL_IDL_17_12_VME/IDL_17_12_TerB5 (R1RB_IDL_17_12_TerB5.1 R2RB_IDL_17_12_TerB5.2), IDL_IDL_17_12_VME/IDL_17_12_TerB6 (R1RB_IDL_17_12_TerB6.1 R2RB_IDL_17_12_TerB6.2), IDL_IDL_17_12_VME/IDL_17_12_TerB7 (R1RB_IDL_17_12_TerB7.1 R2RB_IDL_17_12_TerB7.2), IDL_IDL_17_12_VME/IDL_17_12_TerB8 (R1RB_IDL_17_12_TerB8.1 R2RB_IDL_17_12_TerB8.2), IDL_IDL_17_12_VME/IDL_17_12_TerB9 (R1RB_IDL_17_12_TerB9.1 R2RB_IDL_17_12_TerB9.2), IDL_IDL_17_12_VME/IDL_17_12_TerB10 (R1RB_IDL_17_12_TerB10.1 R2RB_IDL_17_12_TerB10.2), IDL_IDL_17_12_VME/IDL_17_12_TerB11 (R1RB_IDL_17_12_TerB11.1 R2RB_IDL_17_12_TerB11.2), IDL_IDL_17_12_VME/IDL_17_12_TerB12 (R1RB_IDL_17_12_TerB12.1 R2RB_IDL_17_12_TerB12.2), IDL_IDL_17_12_VME/IDL_17_12_TerB13 (R1RB_IDL_17_12_TerB13.1 R2RB_IDL_17_12_TerB13.2), IDL_IDL_17_12_VME/IDL_17_12_TerB14 (R1RB_IDL_17_12_TerB14.1 R2RB_IDL_17_12_TerB14.2), IDL_IDL_17_12_VME/IDL_17_12_TerB15 (R1RB_IDL_17_12_TerB15.1 R2RB_IDL_17_12_TerB15.2), IDL_IDL_17_12_VME/IDL_17_12_TerB16 (R1RB_IDL_17_12_TerB16.1 R2RB_IDL_17_12_TerB16.2), IDL_IDL_17_12_VME/IDL_17_12_TerB17 (R1RB_IDL_17_12_TerB17.1 R2RB_IDL_17_12_TerB17.2), IDL_IDL_17_12_VME/IDL_17_12_TerB18 (R1RB_IDL_17_12_TerB18.1 R2RB_IDL_17_12_TerB18.2), IDL_IDL_17_12_VME/IDL_17_12_TerB19 (R1RB_IDL_17_12_TerB19.1 R2RB_IDL_17_12_TerB19.2), IDL_IDL_17_12_VME/IDL_17_12_TerB20 (R1RB_IDL_17_12_TerB20.1 R2RB_IDL_17_12_TerB20.2), IDL_IDL_17_12_VME/IDL_17_12_TerB21 (R1RB_IDL_17_12_TerB21.1 R2RB_IDL_17_12_TerB21.2), IDL_IDL_17_12_VME/IDL_17_12_TerB22 (R1RB_IDL_17_12_TerB22.1 R2RB_IDL_17_12_TerB22.2), IDL_IDL_17_12_VME/IDL_17_12_TerB23 (R1RB_IDL_17_12_TerB23.1 R2RB_IDL_17_12_TerB23.2), IDL_IDL_17_12_VME/IDL_17_12_TerB24 (R1RB_IDL_17_12_TerB24.1 R2RB_IDL_17_12_TerB24.2), IDL_IDL_17_12_VME/IDL_17_12_TerB25 (R1RB_IDL_17_12_TerB25.1 R2RB_IDL_17_12_TerB25.2)

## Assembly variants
Single-Ended Input: not fitted C2 C4 C9 C10 C19 C20 C22 C24 C29 C30 C39 C40 C42 C45 C50 C52 C54 C59 C60 C69 C70 C72 C74 C79 C80 C89 C90 C92 C95 C100 C102 C104 C109 C110 C119 C120 C122 C124 C129 C130 C139 C140 C142 C145 C150 HS1 R3 R5 R7 R23 R25 R39 R50 R52 R68 R70 R84 R95 R97 R113 R115 R129 R164 R165 R166 R167 R168 R169 R170 R171 R172 R173 R174 R175 R176 R177 R178 TIP1
Differential Input: not fitted C2 C4 C19 C20 C22 C24 C39 C40 C42 C50 C52 C54 C69 C70 C72 C74 C89 C90 C92 C100 C102 C104 C119 C120 C122 C124 C139 C140 C142 C150 HS1 R4 R5 R7 R13 R14 R21 R22 R23 R25 R31 R32 R38 R39 R48 R49 R50 R52 R58 R59 R66 R67 R68 R70 R76 R77 R83 R84 R88 R93 R94 R95 R97 R103 R104 R111 R112 R113 R115 R121 R122 R128 R129 R133 R164 R333 TIP1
